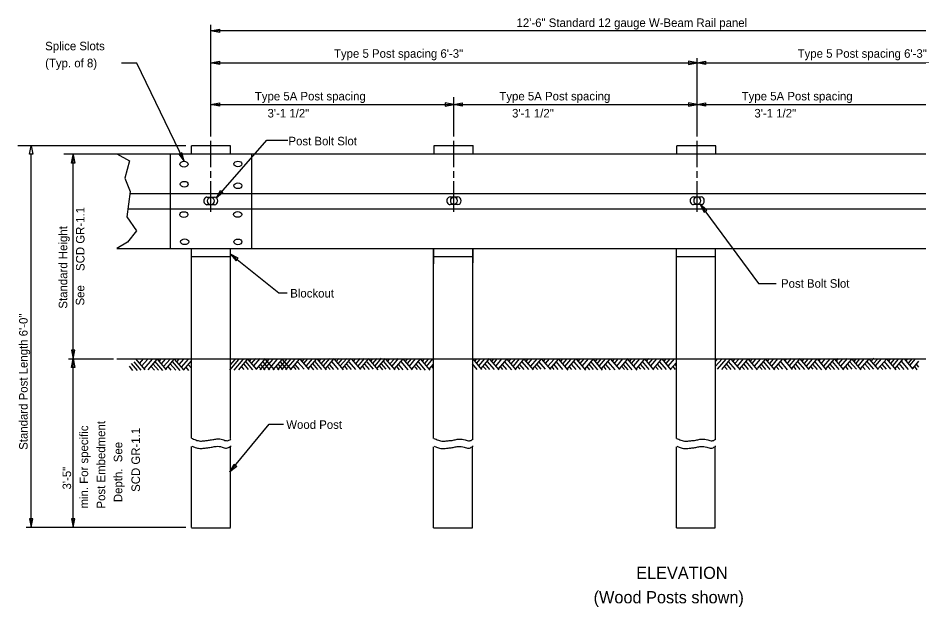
# Model space of a CAD drawing. Extents: x -0.7 to 89.2, y -3.6 to 22.
# Drawn here: x 60.4 to 75.19, y -3.61 to 6.05 of the extents above; entities that cross this region are included whole.
import ezdxf

# ---------------------------------------------------------------- set-up
doc = ezdxf.new("R2010")
doc.units = 0
doc.layers.add('Default', color=7, linetype='Continuous')

msp = doc.modelspace()

# ---------------------------------------------------------------- linework, layer by layer
at = {"layer": 'Default'}
for p, q in [((63.563, 4.108), (63.563, 5.94)), ((79.499, 5.84), (63.563, 5.84)), ((71.544, 4.108), (71.544, 5.394)), ((63.563, 5.316), (71.544, 5.316)), ((71.544, 5.316), (79.499, 5.316)), ((67.55, 4.108), (67.55, 4.754)), ((63.564, 4.631), (67.55, 4.631)), ((67.55, 4.631), (71.544, 4.631)), ((71.544, 4.631), (75.515, 4.631)), ((63.563, 3.601), (63.563, 4.035)), ((67.55, 3.601), (67.55, 4.035)), ((71.544, 3.601), (71.544, 4.035)), ((60.395, 3.956), (63.15, 3.956)), ((63.245, 3.956), (63.883, 3.956)), ((63.245, 3.824), (63.245, 3.955)), ((63.883, 3.828), (63.883, 3.955)), ((67.23, 3.956), (67.867, 3.956)), ((67.23, 3.82), (67.23, 3.956)), ((67.867, 3.824), (67.867, 3.956)), ((71.214, 3.956), (71.851, 3.956)), ((71.214, 3.82), (71.214, 3.955)), ((71.851, 3.82), (71.851, 3.955)), ((60.611, -2.307), (60.611, 3.817)), ((61.146, 3.82), (62.018, 3.82)), ((61.303, 1.433), (61.303, 3.807)), ((62.018, 3.82), (80.505, 3.82)), ((62.018, 3.82), (62.226, 3.705)), ((62.226, 3.705), (62.147, 3.424)), ((62.899, 2.268), (62.899, 3.82)), ((64.237, 2.268), (64.237, 3.822)), ((62.147, 3.424), (62.236, 3.205)), ((63.563, 3.429), (63.563, 3.538)), ((67.55, 3.429), (67.55, 3.538)), ((71.544, 3.429), (71.544, 3.538)), ((63.563, 2.868), (63.563, 3.372)), ((67.55, 2.868), (67.55, 3.372)), ((71.544, 2.868), (71.544, 3.372)), ((62.236, 3.205), (62.183, 2.79)), ((62.231, 3.171), (80.565, 3.171)), ((63.498, 3.112), (63.561, 3.112)), ((63.561, 3.112), (63.624, 3.112)), ((67.489, 3.114), (67.553, 3.114)), ((67.553, 3.114), (67.616, 3.114)), ((71.485, 3.114), (71.548, 3.114)), ((71.548, 3.114), (71.611, 3.114)), ((63.561, 2.987), (63.498, 2.987)), ((63.624, 2.987), (63.561, 2.987)), ((67.553, 2.989), (67.489, 2.989)), ((67.616, 2.989), (67.553, 2.989)), ((71.548, 2.989), (71.485, 2.989)), ((71.611, 2.989), (71.548, 2.989)), ((62.2, 2.92), (80.562, 2.92)), ((62.183, 2.79), (62.343, 2.556)), ((62.343, 2.556), (62.192, 2.373)), ((62.192, 2.373), (62.018, 2.268)), ((62.018, 2.268), (80.505, 2.268)), ((62.018, 2.268), (67.19, 2.268)), ((63.245, -0.845), (63.245, 2.266)), ((63.883, -0.851), (63.883, 2.266)), ((67.22, -0.848), (67.22, 2.268)), ((67.22, 2.268), (67.22, 2.015)), ((67.22, 2.268), (67.22, 2.022)), ((67.861, -0.871), (67.861, 2.268)), ((67.861, 2.268), (67.861, 2.03)), ((71.205, -0.848), (71.205, 2.268)), ((71.846, -0.871), (71.846, 2.268)), ((63.245, 2.135), (63.883, 2.135)), ((67.22, 2.135), (67.861, 2.135)), ((71.205, 2.135), (71.846, 2.135)), ((61.303, 0.457), (61.303, 1.433)), ((61.224, 0.455), (61.961, 0.455)), ((62.018, 0.455), (80.505, 0.455)), ((62.481, 0.279), (62.331, 0.456)), ((62.392, 0.382), (62.454, 0.456)), ((62.431, 0.34), (62.521, 0.445)), ((62.469, 0.291), (62.604, 0.45)), ((62.531, 0.276), (62.681, 0.453)), ((62.834, 0.274), (62.684, 0.45)), ((62.714, 0.415), (62.748, 0.456)), ((62.75, 0.373), (62.819, 0.454)), ((62.786, 0.331), (62.891, 0.454)), ((62.82, 0.288), (62.96, 0.454)), ((63.117, 0.278), (62.967, 0.454)), ((63.005, 0.41), (63.041, 0.453)), ((63.043, 0.366), (63.119, 0.454)), ((63.082, 0.32), (63.195, 0.453)), ((63.873, 0.272), (64.023, 0.448)), ((63.877, 0.455), (67.22, 0.455)), ((63.883, 0.359), (63.959, 0.448)), ((63.943, 0.272), (64.093, 0.448)), ((64.019, 0.278), (64.169, 0.455)), ((64.316, 0.282), (64.177, 0.445)), ((64.196, 0.419), (64.228, 0.456)), ((64.229, 0.378), (64.301, 0.463)), ((64.269, 0.34), (64.372, 0.46)), ((64.31, 0.285), (64.461, 0.462)), ((64.369, 0.275), (64.519, 0.452)), ((64.433, 0.275), (64.583, 0.452)), ((64.605, 0.278), (64.454, 0.455)), ((64.507, 0.276), (64.653, 0.448)), ((64.584, 0.275), (64.732, 0.448)), ((64.663, 0.278), (64.814, 0.455)), ((64.727, 0.278), (64.878, 0.455)), ((64.885, 0.275), (64.737, 0.448)), ((64.795, 0.275), (64.945, 0.452)), ((64.868, 0.275), (65.018, 0.452)), ((65.175, 0.28), (65.032, 0.448)), ((65.06, 0.416), (65.097, 0.459)), ((65.089, 0.381), (65.152, 0.456)), ((65.133, 0.344), (65.231, 0.459)), ((65.162, 0.295), (65.296, 0.453)), ((65.462, 0.275), (65.312, 0.452)), ((65.337, 0.416), (65.373, 0.458)), ((65.372, 0.375), (65.444, 0.459)), ((65.41, 0.34), (65.516, 0.464)), ((65.445, 0.292), (65.588, 0.46)), ((65.742, 0.275), (65.592, 0.451)), ((65.62, 0.412), (65.661, 0.46)), ((65.649, 0.371), (65.724, 0.459)), ((65.687, 0.34), (65.792, 0.463)), ((65.725, 0.299), (65.862, 0.46)), ((66.023, 0.282), (65.872, 0.458)), ((65.906, 0.419), (65.938, 0.457)), ((65.941, 0.375), (66.014, 0.461)), ((65.976, 0.333), (66.085, 0.461)), ((66.017, 0.296), (66.158, 0.461)), ((66.311, 0.275), (66.161, 0.451)), ((66.189, 0.421), (66.22, 0.457)), ((66.221, 0.38), (66.293, 0.464)), ((66.259, 0.342), (66.364, 0.466)), ((66.3, 0.311), (66.427, 0.46)), ((66.586, 0.275), (66.435, 0.451)), ((66.464, 0.414), (66.497, 0.454)), ((66.502, 0.373), (66.575, 0.459)), ((66.54, 0.339), (66.644, 0.461)), ((66.577, 0.291), (66.72, 0.458)), ((66.872, 0.278), (66.721, 0.455)), ((66.755, 0.414), (66.785, 0.449)), ((66.793, 0.383), (66.855, 0.455)), ((66.825, 0.339), (66.924, 0.455)), ((66.861, 0.287), (67.004, 0.456)), ((67.16, 0.271), (67.004, 0.456)), ((67.039, 0.421), (67.069, 0.456)), ((67.074, 0.383), (67.133, 0.454)), ((67.103, 0.332), (67.209, 0.456)), ((68.011, 0.284), (67.861, 0.461)), ((67.863, 0.455), (71.205, 0.455)), ((67.896, 0.42), (67.927, 0.457)), ((67.927, 0.387), (67.983, 0.453)), ((67.961, 0.343), (68.058, 0.457)), ((67.998, 0.299), (68.139, 0.464)), ((68.294, 0.277), (68.144, 0.454)), ((68.176, 0.416), (68.21, 0.457)), ((68.207, 0.387), (68.264, 0.455)), ((68.247, 0.343), (68.342, 0.455)), ((68.284, 0.292), (68.425, 0.457)), ((68.577, 0.277), (68.427, 0.454)), ((68.462, 0.423), (68.485, 0.451)), ((68.493, 0.376), (68.562, 0.457)), ((68.53, 0.339), (68.628, 0.455)), ((68.568, 0.295), (68.706, 0.458)), ((68.857, 0.277), (68.707, 0.454)), ((68.742, 0.42), (68.772, 0.455)), ((68.779, 0.387), (68.837, 0.455)), ((68.816, 0.335), (68.919, 0.457)), ((68.851, 0.295), (68.989, 0.458)), ((69.144, 0.281), (68.993, 0.457)), ((69.028, 0.423), (69.055, 0.455)), ((69.059, 0.383), (69.121, 0.457)), ((69.096, 0.336), (69.196, 0.453)), ((69.134, 0.292), (69.271, 0.453)), ((69.427, 0.273), (69.276, 0.45)), ((69.308, 0.416), (69.342, 0.457)), ((69.345, 0.379), (69.406, 0.451)), ((69.373, 0.332), (69.471, 0.448)), ((69.414, 0.288), (69.557, 0.457)), ((69.719, 0.269), (69.569, 0.446)), ((69.597, 0.42), (69.627, 0.455)), ((69.628, 0.379), (69.692, 0.455)), ((69.659, 0.336), (69.764, 0.459)), ((69.7, 0.288), (69.843, 0.457)), ((69.993, 0.273), (69.843, 0.45)), ((69.877, 0.416), (69.91, 0.455)), ((69.905, 0.376), (69.972, 0.455)), ((69.942, 0.343), (70.039, 0.457)), ((69.977, 0.292), (70.118, 0.459)), ((70.276, 0.28), (70.126, 0.457)), ((70.157, 0.42), (70.187, 0.455)), ((70.191, 0.383), (70.252, 0.455)), ((70.226, 0.339), (70.325, 0.457)), ((70.269, 0.292), (70.412, 0.46)), ((70.559, 0.273), (70.409, 0.45)), ((70.437, 0.416), (70.472, 0.457)), ((70.468, 0.383), (70.532, 0.459)), ((70.509, 0.343), (70.604, 0.455)), ((70.549, 0.295), (70.688, 0.459)), ((70.837, 0.279), (70.687, 0.455)), ((70.717, 0.419), (70.751, 0.46)), ((70.754, 0.38), (70.818, 0.455)), ((70.787, 0.34), (70.886, 0.457)), ((70.827, 0.292), (70.966, 0.455)), ((71.122, 0.279), (70.971, 0.455)), ((71.005, 0.419), (71.036, 0.456)), ((71.04, 0.38), (71.104, 0.455)), ((71.073, 0.339), (71.175, 0.458)), ((71.845, 0.416), (71.88, 0.457)), ((71.846, 0.455), (75.189, 0.455)), ((71.85, 0.335), (71.955, 0.459)), ((71.882, 0.288), (72.021, 0.451)), ((71.949, 0.284), (72.088, 0.447)), ((72.256, 0.275), (72.106, 0.452)), ((72.138, 0.419), (72.17, 0.458)), ((72.166, 0.38), (72.23, 0.454)), ((72.21, 0.339), (72.31, 0.457)), ((72.245, 0.293), (72.384, 0.457)), ((72.538, 0.277), (72.388, 0.454)), ((72.42, 0.421), (72.448, 0.454)), ((72.451, 0.38), (72.511, 0.451)), ((72.49, 0.339), (72.586, 0.453)), ((72.535, 0.296), (72.674, 0.459)), ((72.822, 0.279), (72.671, 0.456)), ((72.704, 0.421), (72.734, 0.455)), ((72.739, 0.38), (72.799, 0.451)), ((72.773, 0.339), (72.871, 0.455)), ((72.813, 0.293), (72.951, 0.457)), ((73.112, 0.282), (72.962, 0.459)), ((72.99, 0.423), (73.017, 0.455)), ((73.034, 0.39), (73.095, 0.462)), ((73.062, 0.344), (73.153, 0.453)), ((73.101, 0.301), (73.236, 0.461)), ((73.387, 0.282), (73.237, 0.459)), ((73.274, 0.423), (73.301, 0.455)), ((73.309, 0.383), (73.37, 0.454)), ((73.341, 0.339), (73.439, 0.454)), ((73.38, 0.293), (73.519, 0.457)), ((73.671, 0.279), (73.521, 0.456)), ((73.551, 0.423), (73.578, 0.455)), ((73.586, 0.383), (73.648, 0.456)), ((73.627, 0.339), (73.728, 0.458)), ((73.664, 0.296), (73.803, 0.459)), ((73.955, 0.277), (73.805, 0.454)), ((73.835, 0.421), (73.869, 0.46)), ((73.872, 0.378), (73.938, 0.456)), ((73.907, 0.337), (74.015, 0.464)), ((73.946, 0.288), (74.084, 0.452)), ((74.241, 0.277), (74.091, 0.454)), ((74.128, 0.421), (74.156, 0.455)), ((74.156, 0.383), (74.218, 0.456)), ((74.188, 0.339), (74.289, 0.457)), ((74.232, 0.296), (74.37, 0.459)), ((74.523, 0.282), (74.373, 0.459)), ((74.404, 0.418), (74.445, 0.466)), ((74.444, 0.379), (74.505, 0.452)), ((74.474, 0.341), (74.572, 0.457)), ((74.514, 0.291), (74.653, 0.454)), ((74.812, 0.279), (74.661, 0.456)), ((74.692, 0.421), (74.722, 0.456)), ((74.725, 0.382), (74.785, 0.453)), ((74.765, 0.347), (74.854, 0.452)), ((74.795, 0.297), (74.931, 0.456)), ((75.095, 0.285), (74.95, 0.456)), ((74.974, 0.421), (75.004, 0.457)), ((75.016, 0.385), (75.077, 0.456)), ((75.041, 0.347), (75.134, 0.456)), ((61.303, -2.307), (61.303, 0.443)), ((62.282, 0.268), (62.225, 0.336)), ((62.357, 0.268), (62.26, 0.383)), ((62.419, 0.269), (62.3, 0.409)), ((62.634, 0.27), (62.578, 0.336)), ((62.701, 0.269), (62.613, 0.372)), ((62.773, 0.268), (62.644, 0.419)), ((62.912, 0.27), (62.859, 0.332)), ((62.986, 0.269), (62.894, 0.376)), ((63.057, 0.267), (62.931, 0.415)), ((63.113, 0.269), (63.242, 0.422)), ((63.201, 0.268), (63.158, 0.32)), ((63.242, 0.302), (63.191, 0.363)), ((64.11, 0.283), (64.072, 0.328)), ((64.181, 0.283), (64.107, 0.369)), ((64.251, 0.279), (64.136, 0.414)), ((64.393, 0.28), (64.352, 0.328)), ((64.454, 0.277), (64.381, 0.362)), ((64.531, 0.279), (64.419, 0.41)), ((64.686, 0.275), (64.638, 0.331)), ((64.743, 0.28), (64.67, 0.366)), ((64.813, 0.28), (64.705, 0.407)), ((64.964, 0.281), (64.918, 0.335)), ((65.019, 0.282), (64.947, 0.366)), ((65.092, 0.285), (64.991, 0.403)), ((65.251, 0.279), (65.201, 0.338)), ((65.319, 0.282), (65.236, 0.379)), ((65.385, 0.283), (65.274, 0.414)), ((65.522, 0.28), (65.478, 0.331)), ((65.58, 0.284), (65.516, 0.359)), ((65.657, 0.282), (65.551, 0.407)), ((65.806, 0.282), (65.761, 0.335)), ((65.873, 0.28), (65.797, 0.369)), ((65.94, 0.282), (65.832, 0.41)), ((66.098, 0.282), (66.056, 0.331)), ((66.166, 0.281), (66.091, 0.369)), ((66.232, 0.286), (66.126, 0.41)), ((66.387, 0.279), (66.336, 0.338)), ((66.439, 0.286), (66.362, 0.376)), ((66.514, 0.28), (66.397, 0.417)), ((66.66, 0.276), (66.619, 0.324)), ((66.719, 0.279), (66.648, 0.362)), ((66.804, 0.279), (66.689, 0.414)), ((66.954, 0.28), (66.914, 0.328)), ((67.016, 0.276), (66.94, 0.366)), ((67.086, 0.27), (66.969, 0.407)), ((67.146, 0.287), (67.217, 0.37)), ((67.219, 0.301), (67.19, 0.336)), ((67.219, 0.348), (67.209, 0.36)), ((67.937, 0.28), (67.857, 0.374)), ((68.08, 0.28), (68.035, 0.333)), ((68.145, 0.284), (68.066, 0.377)), ((68.217, 0.284), (68.101, 0.421)), ((68.355, 0.282), (68.315, 0.329)), ((68.424, 0.282), (68.352, 0.366)), ((68.503, 0.276), (68.39, 0.41)), ((68.642, 0.285), (68.601, 0.333)), ((68.708, 0.28), (68.636, 0.366)), ((68.78, 0.28), (68.673, 0.406)), ((68.925, 0.282), (68.881, 0.333)), ((68.987, 0.286), (68.919, 0.366)), ((69.054, 0.287), (68.947, 0.413)), ((69.2, 0.284), (69.164, 0.325)), ((69.267, 0.282), (69.196, 0.366)), ((69.343, 0.28), (69.236, 0.406)), ((69.486, 0.284), (69.451, 0.325)), ((69.558, 0.284), (69.485, 0.369)), ((69.636, 0.28), (69.525, 0.41)), ((69.785, 0.276), (69.74, 0.329)), ((69.847, 0.284), (69.774, 0.369)), ((69.914, 0.278), (69.805, 0.406)), ((70.054, 0.282), (70.017, 0.325)), ((70.122, 0.278), (70.048, 0.366)), ((70.202, 0.276), (70.088, 0.41)), ((70.351, 0.284), (70.312, 0.329)), ((70.412, 0.275), (70.337, 0.362)), ((70.48, 0.278), (70.371, 0.406)), ((70.623, 0.285), (70.583, 0.331)), ((70.691, 0.282), (70.615, 0.371)), ((70.76, 0.283), (70.65, 0.412)), ((70.906, 0.283), (70.864, 0.331)), ((70.971, 0.283), (70.898, 0.369)), ((71.042, 0.282), (70.933, 0.41)), ((71.116, 0.292), (71.202, 0.392)), ((71.192, 0.281), (71.15, 0.33)), ((71.204, 0.348), (71.186, 0.369)), ((72.04, 0.28), (71.996, 0.331)), ((72.107, 0.281), (72.029, 0.373)), ((72.175, 0.281), (72.063, 0.412)), ((72.325, 0.283), (72.282, 0.333)), ((72.391, 0.282), (72.316, 0.371)), ((72.463, 0.28), (72.351, 0.412)), ((72.612, 0.281), (72.57, 0.331)), ((72.672, 0.284), (72.602, 0.367)), ((72.746, 0.284), (72.639, 0.41)), ((72.887, 0.281), (72.845, 0.331)), ((72.954, 0.286), (72.884, 0.369)), ((73.032, 0.279), (72.914, 0.418)), ((73.172, 0.283), (73.133, 0.329)), ((73.24, 0.282), (73.165, 0.369)), ((73.312, 0.283), (73.2, 0.415)), ((73.45, 0.287), (73.415, 0.329)), ((73.522, 0.281), (73.447, 0.369)), ((73.594, 0.278), (73.482, 0.41)), ((73.739, 0.283), (73.696, 0.334)), ((73.805, 0.284), (73.731, 0.372)), ((73.877, 0.284), (73.768, 0.413)), ((74.025, 0.283), (73.986, 0.329)), ((74.094, 0.287), (74.021, 0.372)), ((74.162, 0.286), (74.056, 0.41)), ((74.303, 0.284), (74.262, 0.332)), ((74.379, 0.283), (74.3, 0.376)), ((74.446, 0.287), (74.335, 0.417)), ((74.595, 0.28), (74.551, 0.332)), ((74.656, 0.285), (74.584, 0.37)), ((74.729, 0.287), (74.624, 0.411)), ((74.875, 0.284), (74.832, 0.334)), ((74.944, 0.283), (74.862, 0.379)), ((75.017, 0.282), (74.902, 0.417)), ((75.087, 0.3), (75.188, 0.419)), ((75.161, 0.279), (75.118, 0.329)), ((75.188, 0.323), (75.148, 0.37)), ((63.883, -0.85), (63.888, -0.85)), ((63.245, -2.312), (63.245, -0.984)), ((63.878, -0.975), (63.893, -0.975)), ((63.883, -2.312), (63.883, -0.979)), ((67.22, -2.315), (67.22, -0.987)), ((67.853, -0.977), (67.868, -0.977)), ((67.858, -2.315), (67.858, -0.981)), ((71.205, -2.315), (71.205, -0.987)), ((71.837, -0.977), (71.852, -0.977)), ((71.842, -2.315), (71.842, -0.981)), ((60.53, -2.307), (63.149, -2.307)), ((63.245, -2.314), (63.883, -2.314)), ((67.22, -2.316), (67.858, -2.316)), ((71.205, -2.316), (71.842, -2.316))]:
    msp.add_line(p, q, dxfattribs=at)
for points in [[(63.703, 5.812), (63.563, 5.84), (63.703, 5.868)], [(63.703, 5.288), (63.563, 5.316), (63.703, 5.344)], [(71.404, 5.288), (71.544, 5.316), (71.404, 5.344)], [(71.684, 5.288), (71.544, 5.316), (71.684, 5.344)], [(63.704, 4.603), (63.564, 4.631), (63.704, 4.659)], [(67.41, 4.603), (67.55, 4.631), (67.41, 4.659)], [(67.69, 4.603), (67.55, 4.631), (67.69, 4.659)], [(71.404, 4.603), (71.544, 4.631), (71.404, 4.659)], [(71.684, 4.603), (71.544, 4.631), (71.684, 4.659)], [(60.583, 3.815), (60.611, 3.955), (60.639, 3.815)], [(61.275, 3.667), (61.303, 3.807), (61.331, 3.667)], [(63.036, 3.814), (63.121, 3.699), (63.087, 3.838)], [(63.761, 3.185), (63.649, 3.095), (63.718, 3.221)], [(71.703, 2.896), (71.595, 2.989), (71.659, 2.862)], [(64.011, 2.112), (63.883, 2.177), (63.976, 2.068)], [(61.275, 0.597), (61.303, 0.457), (61.331, 0.597)], [(61.275, 0.317), (61.303, 0.457), (61.331, 0.317)], [(63.986, -1.309), (63.875, -1.399), (63.943, -1.273)], [(60.583, -2.167), (60.611, -2.307), (60.639, -2.167)], [(61.275, -2.167), (61.303, -2.307), (61.331, -2.167)]]:
    msp.add_lwpolyline(points, close=True, dxfattribs=at)
for points in [[(63.121, 3.699), (62.346, 5.31), (62.092, 5.31)], [(63.649, 3.095), (64.483, 4.047), (64.823, 4.047)], [(71.594, 2.989), (72.554, 1.696), (72.846, 1.696)], [(63.883, 2.177), (64.677, 1.543), (64.812, 1.543)], [(63.875, -1.399), (64.517, -0.613), (64.753, -0.613)]]:
    msp.add_lwpolyline(points, dxfattribs=at)
for centre, major_axis, ratio in [((63.121, 3.652), (-0.0664, 0), 0.705181), ((64.006, 3.655), (-0.0664, 0), 0.705181), ((63.125, 3.323), (-0.0664, 0), 0.705181), ((64.006, 3.298), (-0.0664, 0), 0.705181), ((63.561, 3.049), (0, 0.0625), 0.850089), ((67.553, 3.052), (0, 0.0625), 0.850089), ((71.548, 3.052), (0, 0.0625), 0.850089), ((63.118, 2.824), (-0.0664, 0), 0.705181), ((64.002, 2.827), (-0.0664, 0), 0.705181), ((63.131, 2.379), (-0.0664, 0), 0.705181), ((64.006, 2.377), (-0.0664, 0), 0.705181)]:
    msp.add_ellipse(centre, major_axis=major_axis, ratio=ratio, dxfattribs=at)
for centre, start_param, end_param in [((63.498, 3.049), 0, 3.141593), ((63.624, 3.049), 3.141593, 6.283185), ((67.489, 3.052), 0, 3.141593), ((67.616, 3.052), 3.141593, 6.283185), ((71.485, 3.052), 0, 3.141593), ((71.611, 3.052), 3.141593, 6.283185)]:
    msp.add_ellipse(centre, major_axis=(0, 0.0625), ratio=0.850089, start_param=start_param, end_param=end_param, dxfattribs=at)
for points in [[(63.242, -0.845), (63.316, -0.874), (63.39, -0.892), (63.464, -0.886), (63.523, -0.88), (63.592, -0.868), (63.661, -0.857), (63.755, -0.868), (63.829, -0.886), (63.888, -0.863)], [(67.223, -0.848), (67.297, -0.877), (67.371, -0.894), (67.445, -0.888), (67.504, -0.883), (67.573, -0.871), (67.642, -0.859), (67.735, -0.871), (67.809, -0.888), (67.86, -0.868)], [(71.207, -0.848), (71.281, -0.877), (71.355, -0.894), (71.429, -0.888), (71.488, -0.883), (71.557, -0.871), (71.626, -0.859), (71.72, -0.871), (71.793, -0.888), (71.844, -0.868)], [(63.252, -0.975), (63.306, -0.996), (63.38, -1.013), (63.454, -1.008), (63.513, -1.002), (63.582, -0.99), (63.651, -0.979), (63.745, -0.99), (63.819, -1.008), (63.878, -0.984)], [(67.226, -0.977), (67.281, -0.998), (67.355, -1.016), (67.429, -1.01), (67.488, -1.004), (67.557, -0.993), (67.626, -0.981), (67.72, -0.993), (67.794, -1.01), (67.853, -0.987)], [(71.211, -0.977), (71.265, -0.998), (71.339, -1.016), (71.413, -1.01), (71.472, -1.004), (71.541, -0.993), (71.61, -0.981), (71.704, -0.993), (71.778, -1.01), (71.837, -0.987)]]:
    msp.add_spline(points, degree=3, dxfattribs=at)

# ---------------------------------------------------------------- texts
for s, height, p in [('12\'-6" Standard 12 gauge W-Beam Rail panel', 0.14, (68.581, 5.903)), ('Splice Slots', 0.14, (60.841, 5.521)), ('Type 5 Post spacing 6\'-3"', 0.14, (65.583, 5.398)), ('Type 5 Post spacing 6\'-3"', 0.14, (73.196, 5.398)), ('(Typ. of 8)', 0.14, (60.841, 5.241)), ('Type 5A Post spacing', 0.14, (64.284, 4.698)), ('Type 5A Post spacing', 0.14, (68.299, 4.698)), ('Type 5A Post spacing', 0.14, (72.278, 4.698)), ('    3\'-1 1/2"', 0.14, (64.284, 4.418)), ('    3\'-1 1/2"', 0.14, (68.299, 4.418)), ('    3\'-1 1/2"', 0.14, (72.278, 4.418)), ('Post Bolt Slot', 0.14, (64.836, 3.961)), ('Post Bolt Slot', 0.14, (72.923, 1.624)), ('Blockout', 0.14, (64.865, 1.463)), ('Wood Post', 0.14, (64.8, -0.692)), ('ELEVATION', 0.2, (70.545, -3.155)), ('(Wood Posts shown)', 0.2, (69.846, -3.555))]:
    msp.add_text(s, height=height, dxfattribs=at).set_placement(p)
for s, p in [('SCD GR-1.1', (61.487, 1.899)), ('Standard Height', (61.204, 1.281)), (' See', (61.484, 1.281)), ('Standard Post Length 6\'-0" ', (60.553, -1.036)), ('Post Embedment', (61.827, -1.999)), ('min. For specific', (61.547, -1.999)), ('SCD GR-1.1', (62.398, -1.726)), ('  Depth.  See', (62.107, -1.999)), ('      3\'-5"', (61.267, -1.999))]:
    msp.add_text(s, height=0.14, rotation=90, dxfattribs=at).set_placement(p)

doc.saveas('drawing.dxf')
